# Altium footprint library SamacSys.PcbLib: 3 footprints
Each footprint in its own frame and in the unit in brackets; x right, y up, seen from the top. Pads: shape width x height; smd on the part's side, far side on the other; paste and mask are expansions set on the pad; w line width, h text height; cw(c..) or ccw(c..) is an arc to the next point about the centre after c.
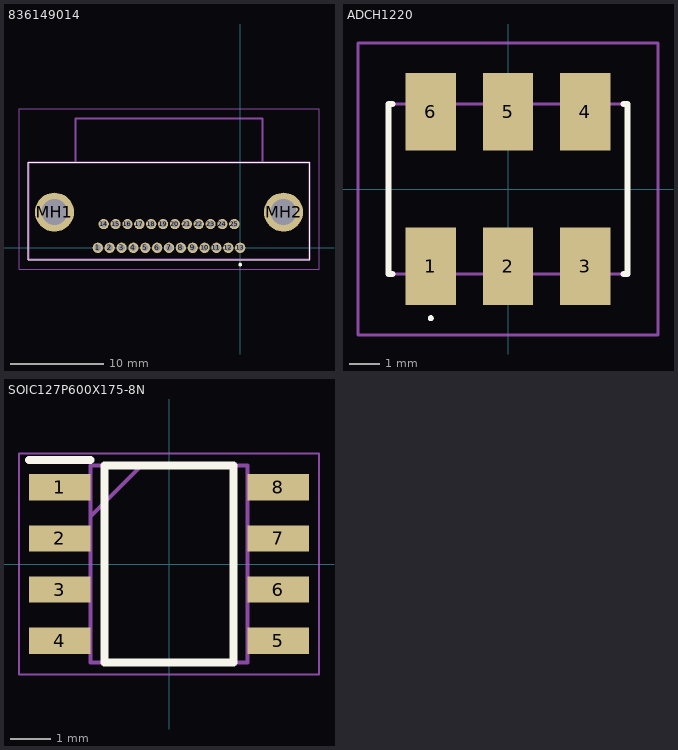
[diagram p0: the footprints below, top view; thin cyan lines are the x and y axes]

## 836149014 [mm]
pads (27):
  round 1.1 hole 0.71: 1(-15.24,0) 2(-13.97,0) 3(-12.7,0) 4(-11.43,0) 5(-10.16,0) 6(-8.89,0) 7(-7.62,0) 8(-6.35,0) 9(-5.08,0) 10(-3.81,0) 11(-2.54,0) 12(-1.27,0) 13(0,0) 14(-14.605,2.54) 15(-13.335,2.54) 16(-12.065,2.54) 17(-10.795,2.54) 18(-9.525,2.54) 19(-8.255,2.54) 20(-6.985,2.54) 21(-5.715,2.54) 22(-4.445,2.54) 23(-3.175,2.54) 24(-1.905,2.54) 25(-0.635,2.54)
  round 4.185 hole 2.79: MH1(-19.875,3.81) MH2(4.635,3.81)
Top Overlay:
  lines w0.1: -22.67,-1.27 7.43,-1.27 7.43,9.13 -22.67,9.13 -22.67,-1.27
  lines w0.2: -0.1,-1.8 ccw(c0,-1.8) 0.1,-1.8 ccw(c0,-1.8) -0.1,-1.8
Mechanical 13:
  lines w0.2: -17.62,9.13 -17.62,13.85 2.38,13.85 2.38,9.13 ; -22.67,-1.27 7.43,-1.27 7.43,9.13 -22.67,9.13 -22.67,-1.27
Mechanical 15:
  lines w0.1: -23.67,-2.27 8.43,-2.27 8.43,14.85 -23.67,14.85 -23.67,-2.27
3D body "83614-9014.stp": height 7.75, standoff -2.85, extent -22.638,-1.067 7.394,13.92

## ADCH1220 [mm]
pads (6):
  rect 1.65x2.54 smd: 1(-2.54,-2.54) 2(0,-2.54) 3(2.54,-2.54) 4(2.54,2.54) 5(0,2.54) 6(-2.54,2.54)
Top Overlay:
  lines w0.1: -2.54,-4.3 ccw(c-2.54,-4.25) -2.54,-4.2 ccw(c-2.54,-4.25) -2.54,-4.3
  lines w0.2: -3.8,-2.795 -3.935,-2.8 -3.935,2.8 -3.8,2.795 ; 3.8,-2.8 3.935,-2.795 3.935,2.795 3.8,2.795
Mechanical 13:
  lines w0.1: -3.935,-2.795 -3.935,2.795 3.935,2.795 3.935,-2.795 -3.935,-2.795
Mechanical 15:
  lines w0.1: -4.935,-4.81 -4.935,4.81 4.935,4.81 4.935,-4.81 -4.935,-4.81
3D body "ADCH-1220+.stp": height 5.33, standoff 0, extent -3.935,-3.645 3.935,3.645

## SOIC127P600X175-8N [mm]
pads (8):
  rect 1.525x0.65 smd: 1(-2.712,1.905) 2(-2.712,0.635) 3(-2.712,-0.635) 4(-2.712,-1.905) 5(2.712,-1.905) 6(2.712,-0.635) 7(2.712,0.635) 8(2.712,1.905)
Top Overlay:
  lines w0.2: -3.475,2.58 -1.95,2.58 ; -1.6,-2.45 1.6,-2.45 1.6,2.45 -1.6,2.45 -1.6,-2.45
Mechanical 13:
  lines w0.1: -1.95,1.18 -0.68,2.45 ; -1.95,-2.45 1.95,-2.45 1.95,2.45 -1.95,2.45 -1.95,-2.45
Mechanical 15:
  lines w0.05: -3.725,-2.75 3.725,-2.75 3.725,2.75 -3.725,2.75 -3.725,-2.75
3D body "NE555DR.stp": height 1.75, standoff 0, extent -3,-2.45 3,2.45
